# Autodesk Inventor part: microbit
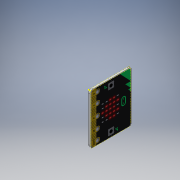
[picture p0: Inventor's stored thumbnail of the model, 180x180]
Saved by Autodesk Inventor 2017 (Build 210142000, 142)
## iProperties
Part Number: microbit
Material: Générique
Document SubType Name: Modeling
Designer: Buhl
Density: 1 g/cm^3
Appearance: Par défaut
Author: Buhl
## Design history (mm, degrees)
sketch "Esquisse1"
  geometry: L1 (3, 0)-(39, 0); L2 (42, -3)-(42, -48); L3 (39, -51)-(3, -51); L4 (0, -48)-(0, -3); A1 r 2 centre (40, -49) between (40, -51) and (42, -49); A2 r 2 centre (40, -2) between (42, -2) and (40, 0); A3 r 3 centre (39, -48) between (39, -51) and (42, -48); A4 r 3 centre (39, -3) between (42, -3) and (39, 0); A5 r 3 centre (3, -3) between (3, 0) and (0, -3); A6 r 3 centre (3, -48) between (0, -48) and (3, -51); 4 further points
  constraints: 12 point on circle, 12 point on line, 12 tangent, 8 end point, 6 centre point, 4 equal radius, 2 parallel, 1 horizontal, 1 perpendicular
  dimensions: "d0" = 42 distance of point (42, -51) point (0, -51); "d1" = 51 distance of point (42, 0) point (42, -51); "d2" = 2 radius of A1 (derived); "d3" = 3 radius of A3
extrude "Extrusion1" new body sketch "Esquisse1" distance "d4" = 1.6; taper "d5" = 0 deg
sketch "Esquisse2"
  geometry: L1 (0.566, 41.203)-(51.277, 41.203); L2 (51.277, 41.203)-(51.277, 0.803); L3 (51.277, 0.803)-(0.566, 0.803); L4 (0.566, 0.803)-(0.566, 41.203); 1 further point; 1 other entity
  constraints: 2 other
  node "Image1"
sketch "Esquisse3"
  geometry: L1 (-50.817, 41.619)-(-0.018, 41.619); L2 (-0.018, 41.619)-(-0.018, 0.936); L3 (-0.018, 0.936)-(-50.817, 0.936); L4 (-50.817, 0.936)-(-50.817, 41.619); 1 further point; 1 other entity
  constraints: 2 other
  node "Image2"
node "Solide1"
